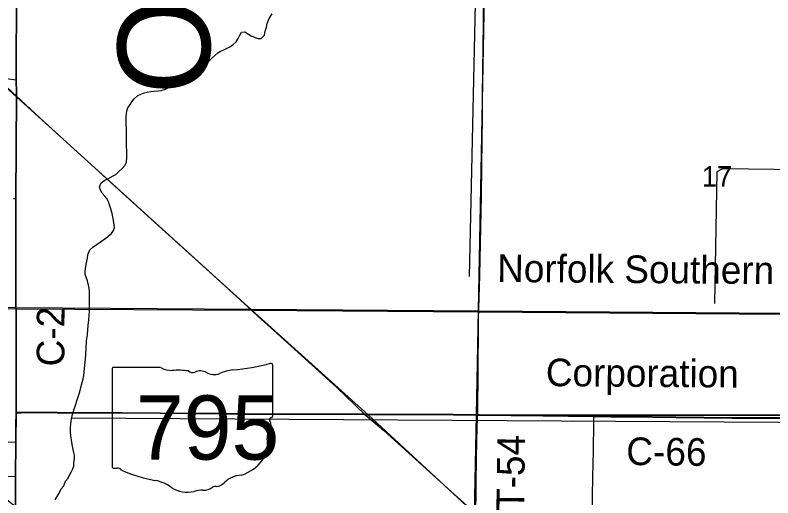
# Model space of a CAD drawing. Extents: x 0 to 34, y 0 to 22.
# Drawn here: x 4.702 to 6.257, y 17.233 to 18.224 of the extents above; entities that cross this region are included whole.
import ezdxf

# ---------------------------------------------------------------- set-up
doc = ezdxf.new("R2010")
doc.units = 0
for name, color, linetype in [('GM_X_City_Street', 7, 'Continuous'), ('GM_X_Corporation', 7, 'Continuous'), ('GM_X_County_Road', 7, 'Continuous'), ('GM_X_County_Road_Text', 7, 'Continuous'), ('GM_X_County_Text', 7, 'Continuous'), ('GM_X_Interstate_Route', 7, 'Continuous'), ('GM_X_Minor_River', 7, 'Continuous'), ('GM_X_Rail_Line', 7, 'Continuous'), ('GM_X_Rail_Line_Text', 7, 'Continuous'), ('GM_X_Section', 7, 'Continuous'), ('GM_X_Section_Text', 7, 'Continuous'), ('GM_X_State_Location', 7, 'Continuous'), ('GM_X_State_Route', 7, 'Continuous'), ('GM_X_State_Shield', 7, 'Continuous'), ('GM_X_Township_Road', 7, 'Continuous'), ('GM_X_Township_Road_Text', 7, 'Continuous')]:
    doc.layers.add(name, color=color, linetype=linetype)

msp = doc.modelspace()

# ---------------------------------------------------------------- linework, layer by layer
at = {"layer": 'GM_X_City_Street'}
msp.add_lwpolyline([(4.6993, 17.8479), (4.7044, 17.8478)], dxfattribs=at)
at = {"layer": 'GM_X_Corporation'}
msp.add_lwpolyline([(4.664, 18.0969), (4.7049, 18.0918), (4.705, 18.0584), (4.7041, 17.8483), (4.7039, 17.6292), (4.7043, 17.4084), (4.7039, 17.3483), (4.7033, 17.2765), (4.6234, 17.2793), (4.7035, 17.2155), (4.7035, 17.0079), (4.4431, 17.0144)], dxfattribs=at)
at = {"layer": 'GM_X_County_Road'}
for p, q in [((4.7052, 18.0579), (4.7051, 18.0967)), ((4.7044, 17.8478), (4.7052, 18.0579)), ((4.7046, 17.4078), (4.7046, 17.6172)), ((4.7035, 17.2759), (4.7041, 17.3477))]:
    msp.add_line(p, q, dxfattribs=at)
for points in [[(4.7051, 18.0967), (4.7051, 18.1097), (4.705, 18.1626), (4.7052, 18.2092), (4.7053, 18.3086), (4.7054, 18.3469), (4.7055, 18.3801), (4.7056, 18.4179)], [(4.7046, 17.6172), (4.7042, 17.6286), (4.7044, 17.8478)], [(4.7041, 17.3477), (4.7042, 17.3819), (4.7046, 17.4078)], [(5.4202, 17.4041), (5.6017, 17.4035), (5.651, 17.4031)], [(5.651, 17.4031), (5.6545, 17.4031), (5.785, 17.4017), (5.8898, 17.4002)], [(5.8898, 17.4002), (5.9248, 17.3997), (5.9621, 17.3993), (6.0584, 17.3982), (6.1734, 17.397), (6.2324, 17.3969), (6.2728, 17.3967), (6.3195, 17.3967), (6.3599, 17.3969), (6.3971, 17.3968), (6.4904, 17.397), (6.537, 17.3967), (6.6147, 17.3964), (6.6286, 17.3964)], [(4.7038, 17.2149), (4.7035, 17.2449), (4.7035, 17.2759)]]:
    msp.add_lwpolyline(points, dxfattribs=at)
at = {"layer": 'GM_X_Interstate_Route'}
for points in [[(4.7035, 17.2155), (4.7033, 17.2455), (4.7033, 17.2765), (4.7039, 17.3483), (4.7039, 17.3824), (4.7043, 17.4084), (4.7044, 17.6177), (4.7039, 17.6292), (4.7041, 17.8483), (4.705, 18.0584), (4.7049, 18.0972), (4.7049, 18.1103), (4.7048, 18.1631), (4.705, 18.2097), (4.7051, 18.3092)], [(4.7051, 18.3092), (4.705, 18.2097), (4.7048, 18.1631), (4.7049, 18.1103), (4.7049, 18.0972), (4.705, 18.0584), (4.7041, 17.8483), (4.7039, 17.6292), (4.7044, 17.6177), (4.7043, 17.4084), (4.7143, 17.4086), (4.7385, 17.4086), (4.7883, 17.4082), (4.9221, 17.408), (5, 17.4073), (5.1214, 17.4063), (5.1743, 17.4057), (5.42, 17.4047), (5.6015, 17.404), (5.6508, 17.4037), (5.6543, 17.4036), (5.7848, 17.4023), (5.8896, 17.4008), (5.9246, 17.4003), (5.9618, 17.3999), (6.0582, 17.3987), (6.1732, 17.3976), (6.2322, 17.3975), (6.2726, 17.3973)], [(6.2726, 17.3973), (6.2322, 17.3975), (6.1732, 17.3976), (6.0582, 17.3987), (5.9618, 17.3999), (5.9246, 17.4003), (5.8896, 17.4008), (5.7848, 17.4023), (5.6543, 17.4036), (5.6508, 17.4037), (5.6015, 17.404), (5.42, 17.4047), (5.1743, 17.4057), (5.1214, 17.4063), (5, 17.4073), (4.9221, 17.408), (4.7883, 17.4082), (4.7385, 17.4086), (4.7143, 17.4086), (4.7043, 17.4084), (4.7039, 17.3824), (4.7039, 17.3483), (4.7033, 17.2765), (4.7033, 17.2455), (4.7035, 17.2155)]]:
    msp.add_lwpolyline(points, dxfattribs=at)
at = {"layer": 'GM_X_Minor_River'}
for points in [[(5.6348, 17.6878), (5.655, 18.6212)], [(4.906, 17.7879), (4.9056, 17.7936), (4.9033, 17.8065), (4.9014, 17.8171), (4.8984, 17.8289), (4.8942, 17.8411), (4.8908, 17.8475), (4.8866, 17.8529), (4.8813, 17.8589), (4.8775, 17.865), (4.8756, 17.8719), (4.879, 17.8798), (4.8862, 17.8855), (4.8972, 17.8912), (4.9037, 17.8943), (4.909, 17.8973), (4.9151, 17.903), (4.9223, 17.9095), (4.9276, 17.9159), (4.9306, 17.9224), (4.9314, 17.933), (4.9314, 17.9475), (4.931, 17.9532), (4.931, 17.9775), (4.9306, 17.9847), (4.9306, 17.9931), (4.9302, 17.9992), (4.9302, 18.0155), (4.9306, 18.0216), (4.9314, 18.0281), (4.9337, 18.0341), (4.9382, 18.041), (4.9416, 18.0463), (4.9469, 18.0528), (4.9542, 18.0592), (4.9606, 18.0623), (4.9671, 18.0645), (4.9735, 18.0664), (4.9807, 18.0676), (4.9864, 18.068), (4.9959, 18.0687), (5.0023, 18.0699), (5.0107, 18.0725), (5.0224, 18.0786), (5.0361, 18.0851), (5.0471, 18.0907), (5.0555, 18.0949), (5.0646, 18.1014), (5.0756, 18.1097), (5.0858, 18.1181), (5.0942, 18.1257), (5.0995, 18.1299), (5.1052, 18.1352), (5.112, 18.1417), (5.1181, 18.147), (5.1238, 18.1504), (5.1306, 18.1534), (5.1442, 18.1603), (5.1496, 18.1641), (5.1556, 18.1698), (5.1602, 18.1762), (5.1632, 18.1835), (5.167, 18.1895), (5.1738, 18.1899), (5.1811, 18.185), (5.1867, 18.1816), (5.1951, 18.1785), (5.2012, 18.1766), (5.2069, 18.1766), (5.2137, 18.1831), (5.2156, 18.1914), (5.2179, 18.1994), (5.2198, 18.2074), (5.2239, 18.2177), (5.23, 18.2272)], [(6.7905, 17.9008), (6.1539, 17.9085), (6.1417, 17.9025), (6.1372, 17.6322)], [(4.7849, 17.2292), (4.7887, 17.236), (4.7925, 17.2425), (4.797, 17.2516), (4.8023, 17.2581), (4.8061, 17.2672), (4.8115, 17.2737), (4.8141, 17.2797), (4.8179, 17.287), (4.8209, 17.293), (4.8228, 17.2991), (4.8232, 17.3048), (4.824, 17.3147), (4.824, 17.3208), (4.8228, 17.3265), (4.8217, 17.3326), (4.8202, 17.3394), (4.8187, 17.3466), (4.8179, 17.3519), (4.8168, 17.3603), (4.816, 17.3679), (4.816, 17.377), (4.8164, 17.3854), (4.8179, 17.3953), (4.8202, 17.4044), (4.8232, 17.4131), (4.8259, 17.4215), (4.8304, 17.4367), (4.835, 17.4508), (4.8388, 17.4652), (4.8418, 17.4774), (4.8433, 17.4838), (4.8441, 17.4926), (4.8456, 17.5055), (4.8468, 17.5176), (4.8475, 17.5275), (4.8479, 17.5404), (4.8487, 17.5553), (4.8509, 17.5682), (4.8517, 17.5781), (4.8524, 17.5868), (4.8536, 17.5986), (4.8543, 17.6085), (4.8547, 17.6149), (4.8551, 17.6233), (4.8551, 17.6567), (4.8543, 17.6632), (4.8532, 17.6701), (4.8506, 17.6788), (4.8479, 17.686), (4.8464, 17.6917), (4.8464, 17.6978), (4.8468, 17.7043), (4.8483, 17.713), (4.8494, 17.7191), (4.8506, 17.7255), (4.8517, 17.7324), (4.8555, 17.7423), (4.8619, 17.748), (4.8684, 17.7529), (4.8767, 17.7582), (4.8821, 17.762), (4.8881, 17.7658), (4.8934, 17.7704), (4.8999, 17.7757), (4.9044, 17.7822), (4.906, 17.7879)], [(6.6035, 17.3858), (4.8182, 17.3966)]]:
    msp.add_lwpolyline(points, dxfattribs=at)
at = {"layer": 'GM_X_Rail_Line'}
msp.add_line((4.7059, 18.0556), (5.1871, 17.6191), dxfattribs=at)
for points in [[(2.1, 20.4531), (2.5585, 20.0312), (3.0884, 19.5461), (3.6994, 18.9771), (4.1763, 18.5403), (4.7059, 18.0556)], [(2.1, 19.6439), (2.1012, 19.6428), (2.4982, 19.2743), (2.9696, 18.8359), (3.3468, 18.4857), (3.702, 18.1547), (3.9505, 17.921), (4.0191, 17.8627), (4.0357, 17.8486), (4.0945, 17.8067), (4.1695, 17.7587), (4.2566, 17.7148), (4.3444, 17.681), (4.4559, 17.6499), (4.5498, 17.6344), (4.6383, 17.6263), (4.7029, 17.6237), (4.7039, 17.6237)], [(2.1, 19.64), (2.4967, 19.2714), (2.9674, 18.8343), (3.3458, 18.483), (3.6997, 18.1544), (3.9489, 17.9193), (4.0176, 17.861), (4.0342, 17.8468), (4.0931, 17.8048), (4.1683, 17.7567), (4.2556, 17.7127), (4.3436, 17.6788), (4.4554, 17.6477), (4.5495, 17.6321), (4.6381, 17.624), (4.7029, 17.6214), (4.7039, 17.6214)], [(4.7039, 17.6237), (5.1874, 17.6209), (5.6534, 17.6172), (5.9221, 17.6153), (6.6307, 17.6096), (7.1327, 17.6059), (7.4891, 17.603), (7.6513, 17.6017), (7.7461, 17.6007), (7.7732, 17.5996), (7.7996, 17.5979), (7.8317, 17.5948), (7.856, 17.5922), (7.8859, 17.5877), (7.9297, 17.5801), (7.9694, 17.5712), (8.019, 17.5585), (8.0883, 17.5388), (8.2893, 17.4822), (8.4661, 17.4324), (8.6481, 17.3808), (8.9, 17.3095)], [(4.7039, 17.6214), (5.1874, 17.6186), (5.6534, 17.6149), (5.9221, 17.613), (6.6307, 17.6073), (7.1327, 17.6036), (7.489, 17.6007), (7.6513, 17.5994), (7.7461, 17.5984), (7.7731, 17.5973), (7.7994, 17.5956), (7.8314, 17.5925), (7.8557, 17.5899), (7.8855, 17.5854), (7.9292, 17.5778), (7.9689, 17.569), (8.0184, 17.5563), (8.0876, 17.5366), (8.2886, 17.48), (8.4655, 17.4302), (8.6474, 17.3785), (8.9, 17.3071)], [(5.1871, 17.6191), (5.4266, 17.4037), (5.6472, 17.1998), (6.051, 16.8348), (6.7774, 16.1806), (7.1287, 15.8668)]]:
    msp.add_lwpolyline(points, dxfattribs=at)
at = {"layer": 'GM_X_Section'}
for points in [[(5.6682, 18.408), (6.6382, 18.4059), (6.6213, 17.4032), (5.6487, 17.4026)], [(6.6213, 17.4032), (6.6138, 16.3837), (5.6285, 16.3977), (5.6487, 17.4026)]]:
    msp.add_lwpolyline(points, close=True, dxfattribs=at)
at = {"layer": 'GM_X_State_Route'}
for points in [[(4.7052, 18.0579), (4.6963, 18.0659), (4.6818, 18.0796), (4.6642, 18.0963)], [(4.6642, 18.0963), (4.6818, 18.0796), (4.6963, 18.0659), (4.7052, 18.0579)], [(5.4202, 17.4041), (5.3624, 17.4595), (5.3118, 17.5055), (5.2679, 17.545), (5.2265, 17.5827), (5.2012, 17.6057), (5.1805, 17.6244), (5.1093, 17.6894), (5.0655, 17.7291), (5.0103, 17.7793), (4.9067, 17.8734), (4.8585, 17.9174), (4.8308, 17.9424), (4.7619, 18.0053), (4.7052, 18.0579)], [(4.7052, 18.0579), (4.7619, 18.0053), (4.8308, 17.9424), (4.8585, 17.9174), (4.9067, 17.8734), (5.0103, 17.7793), (5.0655, 17.7291), (5.1093, 17.6894), (5.1805, 17.6244), (5.2012, 17.6057), (5.2265, 17.5827), (5.2679, 17.545), (5.3118, 17.5055), (5.3624, 17.4595), (5.4202, 17.4041)], [(4.7041, 17.3477), (4.7042, 17.3819), (4.7046, 17.4078)], [(4.7046, 17.4078), (4.7146, 17.408), (4.7387, 17.4081), (4.7885, 17.4077), (4.9224, 17.4075), (5.0002, 17.4068), (5.1216, 17.4058), (5.1745, 17.4052), (5.4202, 17.4041)], [(5.6433, 17.2045), (5.5973, 17.2463), (5.4589, 17.3714), (5.4202, 17.4041)], [(5.4202, 17.4041), (5.4589, 17.3714), (5.5973, 17.2463), (5.6433, 17.2045)], [(4.4635, 17.3564), (4.5221, 17.354), (4.5349, 17.3534), (4.5637, 17.3523), (4.614, 17.3501), (4.6641, 17.348), (4.7041, 17.3477)]]:
    msp.add_lwpolyline(points, dxfattribs=at)
at = {"layer": 'GM_X_State_Shield'}
for p, q in [((5.2308, 17.4013), (5.2308, 17.506)), ((4.9012, 17.4976), (4.9012, 17.2975)), ((5.001, 17.501), (4.9044, 17.501)), ((5.2308, 17.4013), (5.2308, 17.4013))]:
    msp.add_line(p, q, dxfattribs=at)
for centre, major_axis, start_param, end_param in [((5.1134, 17.7739), (0.3495, 0), 4.814394, 5.042369), ((5.2271, 17.5064), (0.00367, 0), 6.141152, 7.989035), ((4.905, 17.498), (0.00382, 0), 1.712693, 3.28349), ((5.024, 17.5243), (0.037, 0), 4.042523, 4.731795), ((5.0362, 17.3887), (0.133, 0), 1.404758, 1.657858), ((5.0664, 17.4991), (0.0107, 0), 3.836095, 5.185415), ((5.0821, 17.4759), (0.0222, 0), 0.950623, 2.079405), ((5.1108, 17.5077), (0.0267, 0), 4.081561, 5.145723), ((5.158, 17.4399), (0.0703, 0), 1.699011, 2.107814), ((5.2299, 17.3936), (0.00568, 0), 1.883978, 3.671073), ((5.2269, 17.4009), (0.00393, 0), 5.05454, 6.418171), ((5.1938, 17.3804), (0.0341, 0), 5.934695, 6.695948), ((5.2439, 17.3575), (0.0248, 0), 2.387724, 3.262537), ((5.133, 17.3442), (0.0874, 0), 5.101752, 6.440018), ((4.905, 17.297), (0.00385, 0), 3.00124, 4.508301), ((4.9056, 17.3175), (0.0294, 0), 4.665946, 4.897461), ((4.9116, 17.2859), (0.0106, 0), 0.519207, 1.627899), ((5.0454, 17.4657), (0.2524, 0), 4.195997, 4.488961), ((5.1698, 17.2413), (0.0479, 0), 1.647645, 2.488434), ((4.9702, 17.2076), (0.079, 0), 0.823519, 1.323587), ((5.0882, 17.27), (0.0267, 0), 4.691044, 5.507374), ((5.1124, 17.2506), (0.00752, 0), 1.147584, 2.315152), ((5.1092, 17.2781), (0.0282, 0), 4.937069, 5.64225), ((5.0556, 17.2849), (0.0501, 0), 4.026481, 4.996735), ((5.0846, 17.2157), (0.0412, 0), 1.495662, 1.94098)]:
    msp.add_ellipse(centre, major_axis=major_axis, ratio=0.8, start_param=start_param, end_param=end_param, dxfattribs=at)
at = {"layer": 'GM_X_Township_Road'}
for points in [[(5.651, 17.4031), (5.6514, 17.4089), (5.6523, 17.4936), (5.653, 17.5863), (5.6531, 17.5993), (5.6559, 17.6894), (5.6589, 17.8542), (5.6596, 17.9133), (5.6606, 17.9693), (5.661, 18.0128), (5.6614, 18.0595), (5.6625, 18.159), (5.6632, 18.2087), (5.6646, 18.33), (5.6649, 18.386), (5.6651, 18.4051), (5.6652, 18.4079)], [(5.6471, 17.201), (5.6474, 17.2107), (5.6478, 17.2174), (5.648, 17.2345), (5.6485, 17.2638), (5.6492, 17.312), (5.6498, 17.3519), (5.6507, 17.3982), (5.651, 17.4031)], [(5.8369, 17.0285), (5.839, 17.031), (5.8439, 17.0368), (5.8542, 17.048), (5.8663, 17.0606), (5.8762, 17.0708), (5.8787, 17.074), (5.8807, 17.0767), (5.8821, 17.079), (5.8833, 17.0814), (5.8844, 17.0842), (5.8851, 17.088), (5.8856, 17.0922), (5.8857, 17.1013), (5.8861, 17.1602), (5.8868, 17.2346), (5.8877, 17.2779), (5.8881, 17.3027), (5.8887, 17.3304), (5.8894, 17.3862), (5.8897, 17.3972), (5.8898, 17.4002)]]:
    msp.add_lwpolyline(points, dxfattribs=at)

# ---------------------------------------------------------------- texts
at = {"layer": 'GM_X_County_Road_Text'}
for s, rotation, p in [('C-2', 89.874, (4.8035, 17.5029)), ('C-66', 359.3129, (5.9559, 17.3006))]:
    msp.add_text(s, height=0.05682, rotation=rotation, dxfattribs=at).set_placement(p)
at = {"layer": 'GM_X_County_Text'}
msp.add_text('OTTAWA COUNTY', height=0.189394, rotation=89.9764, dxfattribs=at).set_placement((5.1023, 18.0616))
at = {"layer": 'GM_X_Rail_Line_Text'}
for s, rotation, p in [('Norfolk Southern', 359.5598, (5.6912, 17.6764)), ('Corporation', 359.5728, (5.7911, 17.4625))]:
    msp.add_text(s, height=0.056629, rotation=rotation, dxfattribs=at).set_placement(p)
at = {"layer": 'GM_X_Section_Text'}
msp.add_text('17', height=0.04186, rotation=0, dxfattribs=at).set_placement((6.1113, 17.8724))
at = {"layer": 'GM_X_State_Location'}
for s in ['s', 'r']:
    msp.add_text(s, height=0.000189, dxfattribs=at).set_placement((5.0623, 17.3842))
msp.add_text('795', height=0.000189, rotation=0, dxfattribs=at).set_placement((4.9954, 17.3705))
at = {"layer": 'GM_X_State_Shield'}
msp.add_text('795', height=0.13184, dxfattribs=at).set_placement((4.9503, 17.3116))
at = {"layer": 'GM_X_Township_Road_Text'}
msp.add_text('T-54', height=0.05682, rotation=89.2903, dxfattribs=at).set_placement((5.7465, 17.2058))

doc.saveas('drawing.dxf')
